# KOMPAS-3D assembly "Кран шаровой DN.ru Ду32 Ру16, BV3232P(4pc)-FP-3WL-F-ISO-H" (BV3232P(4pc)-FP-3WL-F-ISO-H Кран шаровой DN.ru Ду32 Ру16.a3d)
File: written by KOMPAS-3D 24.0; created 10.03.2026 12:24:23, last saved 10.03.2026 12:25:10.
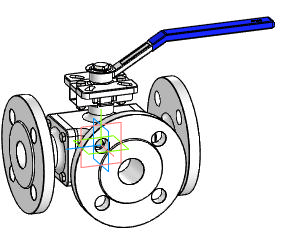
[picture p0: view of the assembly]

Document properties: Автор: R2D2; Полное имя файла: E:\Работа\Зайцев\BV3232P(4pc)-FP-3WL-F-ISO-H Кран шаровой DN.ru Ду15-100 Ру16\DN32\исходные материалы\BV3232P(4pc)-FP-3WL-F-ISO-H Кран шаровой DN.ru Ду32 Ру16.a3d

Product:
- Component [assembly]: Сборка1  | qty 1  | Масса: 10.961303; Автор: R2D2; source file: dn32_3d_step.a3d
- Part/product: Кран шаровой DN.ru Ду32 Ру16  | designation BV3232P(4pc)-FP-3WL-F-ISO-H
    Масса: 9.3
    Раздел спецификации: Прочие изделия
    Примечание: D160-36358

Referenced files in E:\Работа\Зайцев\BV3232P(4pc)-FP-3WL-F-ISO-H Кран шаровой DN.ru Ду15-100 Ру16\DN32\исходные материалы\: dn32_3d_step.a3d
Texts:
  BV3232P(4pc)-FP-3WL-F-ISO-H
  Сборка1 Сборка1
  Ось Z.Начало координат
  Ось Y.Начало координат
